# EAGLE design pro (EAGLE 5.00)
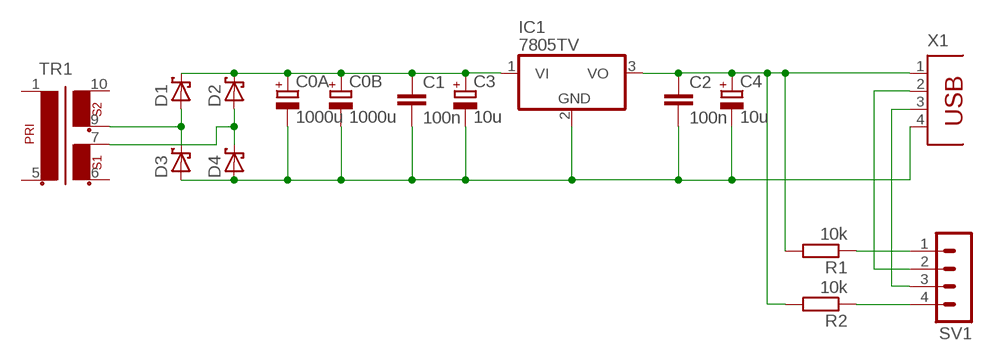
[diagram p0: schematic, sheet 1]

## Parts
C0A  1000u  CPOL-EUE5-13  [E5-13]
C0B  1000u  CPOL-EUE5-13  [E5-13]
C1  100n  C2.5/2  [C2.5-2]
C2  100n  C2.5/2  [C2.5-2]
C3  10u  CPOL-EUE2-5  [E2-5]
C4  10u  CPOL-EUE2-5  [E2-5]
D1  SCHOTTKY-DIODEDO35-7  [DO35-7]
D2  SCHOTTKY-DIODEDO35-7  [DO35-7]
D3  SCHOTTKY-DIODEDO35-7  [DO35-7]
D4  SCHOTTKY-DIODEDO35-7  [DO35-7]
IC1  7805TV  [TO220V]
R1  10k  R-EU_0204/5  [0204/5]
R2  10k  R-EU_0204/5  [0204/5]
SV1  MA04-1  [MA04-1]
TR1  EI42-2  [EI42-2]
X1  PN87520  [PN87520]

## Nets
N$1: C0A.+ C0B.+ C1.1 C3.+ D1.C D2.C IC1.1(VI)
N$2: D2.A D4.C TR1.7
N$3: D1.A D3.C TR1.9
N$4: SV1.2 X1.2
N$5: SV1.3 X1.3
N$6: C2.1 C4.+ IC1.3(VO) R1.2 R2.2 X1.1
N$7: R1.1 SV1.1
N$8: C0A.- C0B.- C1.2 C2.2 C3.- C4.- D3.A D4.A IC1.2(GND) X1.4
N$9: R2.1 SV1.4
Unconnected: TR1.1 TR1.5 TR1.6 TR1.10

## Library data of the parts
C0A C0B C3 C4 = rcl:CPOL-EU: POLARIZED CAPACITOR, European symbol
C1 C2 = capacitor-wima:C: CAPACITOR
D1-D4 = diode:SCHOTTKY-DIODE: Schottky Diode
IC1 = linear:78*: Positive VOLTAGE REGULATOR Source: http://cache.national.com/ds/LM/LM78L05.pdf http://www.fairchildsemi.com/ds/LM/LM7805.pdf
R1 R2 = rcl:R-EU_: RESISTOR, European symbol
SV1 = con-lstb:MA04-1: PIN HEADER
TR1 = trafo:EI42-2: TRANSFORMER 1 primary winding, 2 secondary windings ERA
X1 = con-berg:PN87520: BERG USB connector

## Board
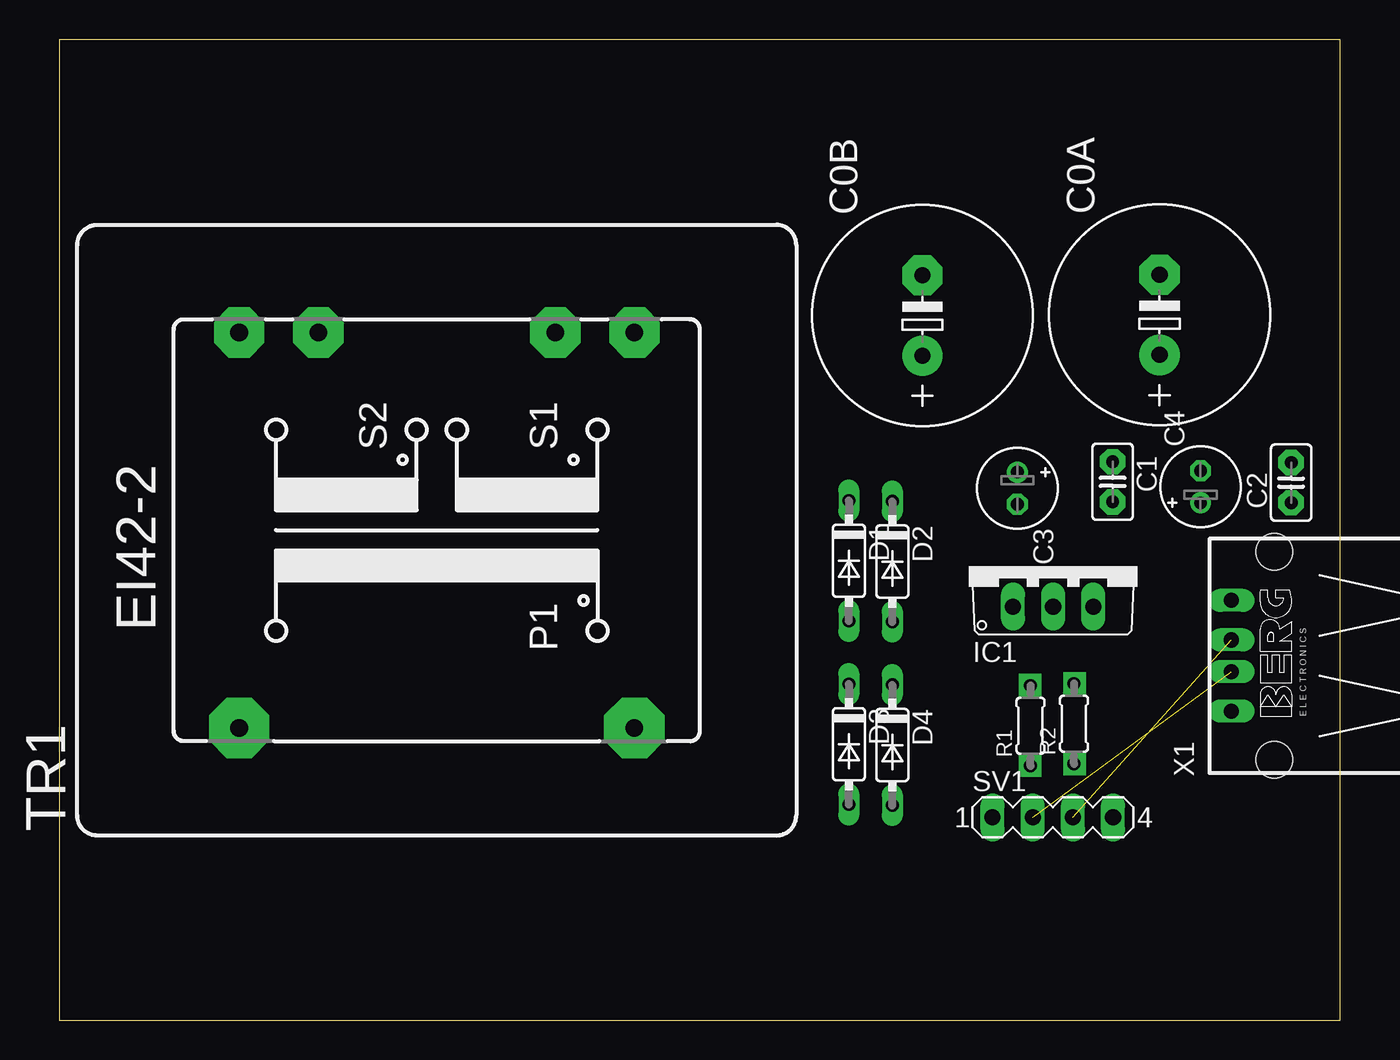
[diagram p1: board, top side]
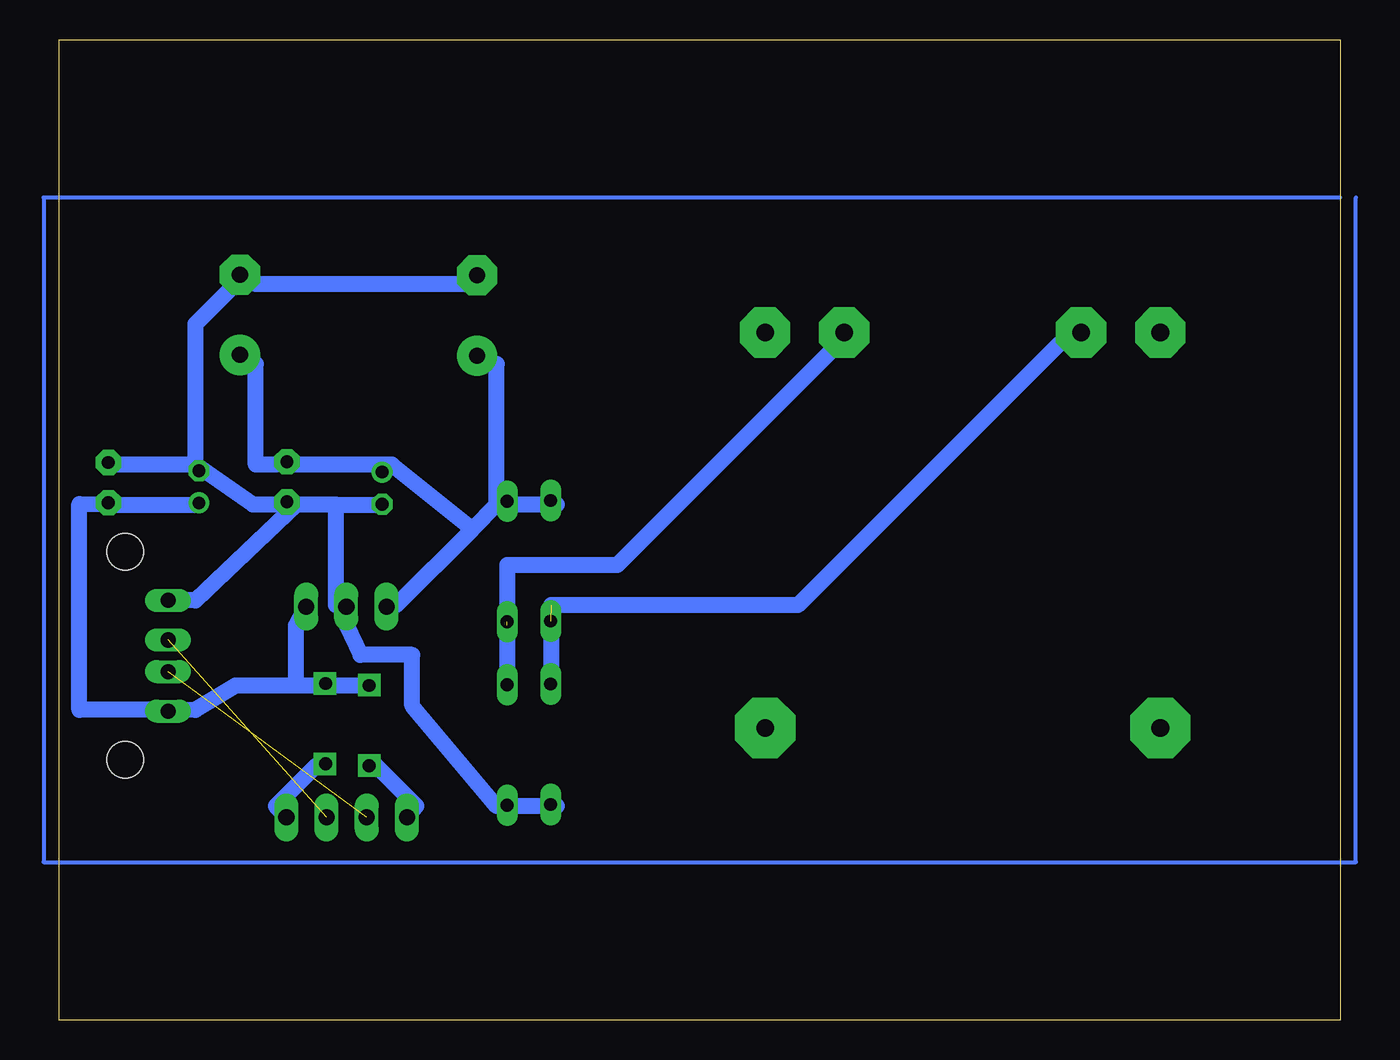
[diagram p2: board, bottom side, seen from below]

Size 81 x 62 mm. Coordinates in mm from the lower left corner, seen from the top.
Outline: 0,0 81,0 81,62 0,62 0,0
Copper layers (1*16): Top 0.035mm / dielectric 1.5mm / Bottom 0.035mm
Design rules "default": minimum track width 10mil, minimum drill 24mil, track to track 8mil, track to pad 8mil, pad to pad 8mil, via to via 8mil, smd to smd 8mil, copper to edge 40mil, drill to drill 8mil, minimum pad ring 10mil, minimum via ring 8mil, stop-mask expansion 4mil, vias tented up to drill 0mil, thermal gap 10mil

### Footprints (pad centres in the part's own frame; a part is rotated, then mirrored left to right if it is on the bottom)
E5-13 = drill 1.016 pad 2.54 round: + -2.54,0 | drill 1.016 pad 2.54 octagon: - 2.54,0
C2.5-2 = drill 0.813 pad 1.6 octagon: 1 -1.27,0; 2 1.27,0
E2-5 = drill 0.813 pad 1.27 round: + -1.016,0 | drill 0.813 pad 1.27 octagon: - 1.016,0
DO35-7 = drill 0.813 long: A 3.81,0; C -3.81,0
TO220V = drill 1.016 long: 1 -2.54,-2.54; 2 0,-2.54; 3 2.54,-2.54
0204/5 = drill 0.813 octagon: 1 -2.54,0; 2 2.54,0
MA04-1 = drill 1.016 long: 1 -3.81,0; 2 -1.27,0; 3 1.27,0; 4 3.81,0
EI42-2 = drill 1.118 pad 3.81 octagon: 1 -12.497,12.497; 5 -12.497,-12.497 | drill 1.118 pad 3.175 octagon: 6 12.497,-12.497; 7 12.497,-7.493; 9 12.497,7.493; 10 12.497,12.497
PN87520 = drill 0.95 long: 1 -3.5,2.71; 2 -1,2.71; 3 1,2.71; 4 3.5,2.71 | hole 2.3: -6.57,0; 6.57,0

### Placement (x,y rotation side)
C0A  69.58,44.6 90 top
C0B  54.58,44.55 90 top
C1  66.61,34.04 270 top
C2  77.9,33.99 90 top
C3  60.58,33.64 270 top
C4  72.17,33.72 90 top
D1  49.93,29.05 270 top
D2  52.68,29 270 top
D3  49.93,17.45 270 top
D4  52.68,17.4 270 top
IC1  62.85,28.69 0 top
R1  61.42,18.62 90 top
R2  64.17,18.75 90 top
SV1  62.83,12.83 0 top
TR1  23.87,30.98 90 top
X1  76.84,23.04 90 top

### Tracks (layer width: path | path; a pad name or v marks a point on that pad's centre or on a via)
N$1
  Bottom 0.254: D1.C 49.53,32.59 | 59.96,35.13 C3.+
  Bottom 1.016: C0A.+ 68.58,41.48 68.58,35.13 67.31,35.13 C1.1 66.04,35.13 59.96,35.13 54.88,31.05 | 49.53,32.59 52.07,32.59 D2.C 53.34,32.59 | 53.34,32.59 54.88,31.05 | 54.88,31.05 59.69,26.24 IC1.1 | 53.34,32.59 53.34,41.48 C0B.+
N$2  (1 unrouted)
  Bottom 1.016: TR1.7 31.75,42.75 45.72,28.78 52.67,28.78 52.67,24.97 52.7,24.97 52.7,21.21 | 52.7,21.2 52.7,21.21 | 52.7,21.21 D4.C
N$3  (1 unrouted)
  Bottom 1.016: TR1.9 17.78,42.75 34.29,26.24 49.9,26.24 49.9,21.26 | 49.9,21.26 49.9,21.1 | 49.9,21.26 D3.C
N$4  (1 unrouted)
N$5  (1 unrouted)
N$6
  Bottom 0.254: 72.39,32.59 C4.+ | R1.2 60.96,21.16 | 64.77,21.16 R2.2 | X1.1 73.66,19.62
  Bottom 1.016: 77.47,32.59 72.39,32.59 | R1.2 64.77,21.16 66.04,21.16 | 66.04,21.16 69.85,21.16 72.39,19.62 X1.1 | 66.04,21.16 66.04,24.97 IC1.3 | 77.47,32.59 77.47,32.62 79.74,32.65 79.74,19.62 73.66,19.62 | 77.47,32.59 C2.1
N$7
  Bottom 0.254: 60.96,16.08 R1.1
  Bottom 1.016: 60.96,16.08 58.42,13.54 SV1.1
N$8
  Bottom 0.254: 77.47,35.13 C2.2 | D3.A 49.53,13.54 | 52.07,13.54 D4.A | 66.04,32.59 C1.2 | 72.39,35.13 C4.-
  Bottom 1.016: C0B.- 54.61,46.56 68.58,46.56 C0A.- 69.85,46.56 72.39,44.02 72.39,35.13 | 72.39,35.13 77.47,35.13 | 49.53,13.54 52.07,13.54 | 63.5,32.59 66.04,32.59 72.39,26.54 X1.4 | 63.5,32.59 60.96,32.59 C3.- | 63.5,32.59 63.5,26.24 IC1.2 62.83,24.97 61.96,23.1 58.69,23.1 58.69,19.89 53.34,13.54 D4.A | 72.39,35.13 68.75,32.59 67.31,32.59 C1.2
N$9
  Bottom 1.016: R2.1 64.77,16.08 67.31,13.54 SV1.4
N$10  (via drill 0.6 pad 1.42)
  other vias: 61.4,21.2
N$11  (via drill 0.6 pad 1.42)
  other vias: 64.2,21.3
N$12  (via drill 0.6 pad 1.42)
  other vias: 64.2,16.2
N$13  (via drill 0.6 pad 1.42)
  other vias: 61.4,16.1
N$14
  Bottom 0.254: 0,52 82,52 82,10 -1,10 -1,52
